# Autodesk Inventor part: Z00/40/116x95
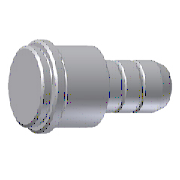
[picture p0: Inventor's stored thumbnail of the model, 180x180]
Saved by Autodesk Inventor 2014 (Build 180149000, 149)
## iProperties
IsCustomPart: 0
Created: 2009-11
Part Number: Z00/40/116x95
Material: DIN 1.7131
Description: guide pillar
Document SubType Name: Modeling
Designer: gaom
Standard Revision: 1
Manufacturer: HASCO
Language: en-US
Size Designation: 40-116x95
Categories: <MemberInstance><Categories><Category DisplayName="Mold" InternalName="349578f2-f4d4-4954-8c09-8e99297a61c0" Mnemonic="MOLD"><Category DisplayName="Guide Compon
Mass: 4.19143 g
Surface Area: 17.8137 cm^2
Volume: 4.19143 cm^3
Density: 7.85 g/cm^3
Appearance: Steel
Author: gaom
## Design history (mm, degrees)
body "Solid1"
revolve "Revolution1" stored, may be unused: angle "d100" = 90 deg
chamfer "Chamfer1" distance "d106" = 0.5; stored, may be unused: second distance "d107" = 2, angle "d108" = 45 deg
fillet "Fillet1" dims "d109" = 0.3
revolve "Revolution2" stored, may be unused: angle "d126" = 90 deg
sketch "Sketch1"
  geometry: L1 (0, -42.393)-(0, 14.066) reference; L2 (0, 22)-(27, 22); L3 (27, 22)-(27, 11); L4 (26.5, 10)-(30, 10); L5 (30, 10)-(30, 0); L6 (30, 0)-(26.5, 0); L7 (27, -1)-(27, -104); L8 (27, -104)-(27, -104); L9 (27, -104)-(27, -106); L10 (27, -106)-(20, -106); L11 (20, -194)-(18.522, -199.518); L12 (16.59, -201)-(0, -201); L13 (20, -106)-(20, -194); L14 (26.5, 0)-(26.5, -1); L15 (26.5, -1)-(27, -1); L16 (26.5, 11)-(27, 11); L17 (26.5, 11)-(26.5, 10); L18 (0, 22)-(0, -201); A1 r 2 centre (16.59, -199) between (16.59, -201) and (18.522, -199.518); 1 further point
  constraints: 38 end point, 7 perpendicular, 6 parallel, 2 collinear, 2 point on circle, 2 point on line, 2 tangent, 2 vertical alignment, 1 centre point, 1 horizontal alignment
  dimensions: "d73" = 10 distance between parallel lines of L6 L4 (derived); "d74" = 12 distance between parallel lines of L2 L4 (derived); "d75" = 116 distance between parallel lines of L10 L4 (derived); "d76" = 2 distance between parallel lines of L10 L8; "d77" = 60 diameter of L5 L1 (derived); "d78" = 95 distance between parallel lines of L12 L10 (derived); "d79" = 54 diameter of L3 L1 (derived); "d89" = 7 distance from line of L12 L11.start (derived); "d92" = 40 diameter of L13 L1 (derived); "d94" = 54 diameter of L7 L1 (derived); "d97" = 2 radius of A1; "d110" = 0.5 distance between parallel lines of L7 L14; "d111" = 1 distance from line of L6.end L15; "d112" = 0.5 distance between parallel lines of L3 L17; "d113" = 1 distance between parallel lines of L4 L16; "d114" = 54 diameter of L9 L18 (derived); "d120" = 15 deg angle of L13 L11
sketch "Sketch2"
  geometry: L1 (-16.59, -201)-(16.59, -201) reference; L2 (0, -40.8)-(0, 6.8) reference; C1 r 2.5 at (20.5, -135.333); C2 r 2.5 at (20.5, -164.667); 1 further point
  constraints: 2 centre point, 1 equal radius, 1 vertical alignment
  dimensions: "d121" = 5 diameter of C1 (derived); "d122" = 36.3333 distance from line of L1 C2.centre (derived); "d123" = 65.6667 distance from line of L1 C1.centre (derived); "d129" = 41 diameter of C1.centre L2 (derived)
other parameters: "d2" = 54 [user parameter], "l2" = 12 [user parameter], "A_" = 116 [user parameter], "B" = 95 [user parameter], "d91" = 8, "d101" = 0, "d103" = 0, "ob" = 7 [user parameter], "d2_1" = 54 [user parameter], "d2_2" = 54 [user parameter], "B1" = 36.3333 [user parameter], "G1" = 65.6667 [user parameter], "d128" = 0, "L_" = 211 [user parameter]
